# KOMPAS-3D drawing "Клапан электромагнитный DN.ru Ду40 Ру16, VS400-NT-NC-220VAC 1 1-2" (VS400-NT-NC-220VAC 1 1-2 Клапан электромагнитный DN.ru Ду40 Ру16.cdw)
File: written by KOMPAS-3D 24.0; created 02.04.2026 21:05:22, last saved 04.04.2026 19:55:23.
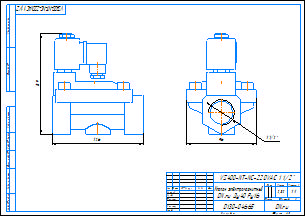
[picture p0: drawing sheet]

Document properties: c3d_UniqueCompID: ef56311e-7521-43dc-8291-0e6108b3d81d; Обозначение: VS400-ET-NC-220VAC 1; Наименование: Клапан электромагнитный DN.ru Ду25 Ру16; Автор: artio; Класс точности: c; Знак неуказанной шероховатости: Шероховатость не задана; Рассекать на разрезах: Да; c3d_UniqueCompID: ef56311e-7521-43dc-8291-0e6108b3d81d; Обозначение: VS400-ET-NC-220VAC 1-2; Наименование: Клапан электромагнитный DN.ru Ду15 Ру16; Автор: artio; Класс точности: c; Знак неуказанной шероховатости: Шероховатость не задана; Рассекать на разрезах: Да; c3d_UniqueCompID: ef56311e-7521-43dc-8291-0e6108b3d81d; Обозначение: VS400-ET-NC-220VAC 3-4; Наименование: Клапан электромагнитный DN.ru Ду20 Ру16; Автор: artio; Класс точности: c; Знак неуказанной шероховатости: Шероховатость не задана; Рассекать на разрезах: Да; c3d_UniqueCompID: ef56311e-7521-43dc-8291-0e6108b3d81d; Обозначение: VS400-ET-NC-220VAC 1 1-4; Наименование: Клапан электромагнитный DN.ru Ду32 Ру16; Автор: artio; Класс точности: c; Знак неуказанной шероховатости: Шероховатость не задана; Рассекать на разрезах: Да; c3d_UniqueCompID: ef56311e-7521-43dc-8291-0e6108b3d81d; Обозначение: VS400-ET-NC-220VAC 3-8; Наименование: Клапан электромагнитный DN.ru Ду10 Ру16; Автор: artio; Класс точности: c; Знак неуказанной шероховатости: Шероховатость не задана; Рассекать на разрезах: Да; c3d_UniqueCompID: ef56311e-7521-43dc-8291-0e6108b3d81d; Обозначение: VS400-ET-NC-220VAC 1 1-2; Наименование: Клапан электромагнитный DN.ru Ду40 Ру16; Автор: artio; Класс точности: c; Знак неуказанной шероховатости: Шероховатость не задана; Рассекать на разрезах: Да; Автор: artio; Форматы листов документа: A3; Полное имя файла: VS400-NT-NC-220VAC 1 1-2 Клапан электромагнитный DN.ru Ду40 Ру16.m3d; Масса: 2.321; Наименование: Клапан электромагнитный DN.ru Ду40 Ру16; Количество листов документа: 1; Примечание: D130-04665

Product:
- Body: Тело 1  | qty 1
    Масса: 4.144257
- Part/product: Клапан электромагнитный DN.ru Ду40 Ру16  | designation VS400-NT-NC-220VAC 1 1-2
    Масса: 2.321
    Раздел спецификации: Прочие изделия
    Примечание: D130-04665
    additional columns: ef56311e-7521-43dc-8291-0e6108b3d81d; VS400-ET-NC-220VAC 1 1-2; artio; c; Шероховатость не задана; Да

Views: Вид 1, Спереди
Referenced files in C:\Users\artio\OneDrive\Рабочий стол\Клапан электромагнитный DN.ru VS4x-xT-NC-x\DN10\: VS400-ET-NC-220VAC 3-8 Клапан электромагнитный DN.ru Ду10 Ру16.m3d, VS400-ET-NC-220VAC 3-8 Клапан электромагнитный DN.ru Ду10 Ру16.cdw
Referenced files in C:\Users\artio\OneDrive\Рабочий стол\Клапан электромагнитный DN.ru\VS400-NT-NC\VS400-NT-NC-220VAC\: VS400-NT-NC-220VAC 1 1-2 Клапан электромагнитный DN.ru Ду40 Ру16.m3d
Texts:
  VS400-NT-NC-220VAC 1 1-2
  Клапан электромагнитный
  DN.ru Ду40 Ру16
  VS400-NT-NC-220VAC 1 1/2"
  VS400-NT-NC-220VAC 1 1/2"-
  Клапан электромагнитный DN.ru Ду40 Ру16
  VS400-NT-NC-220VAC 1 1-2 Клапан электромагнитный DN.ru Ду40 Ру16
Dimensions and other numbers on the sheet: 0; 3; 2; 4; 96; 1 1/2"; 1:1; 1; 2,32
